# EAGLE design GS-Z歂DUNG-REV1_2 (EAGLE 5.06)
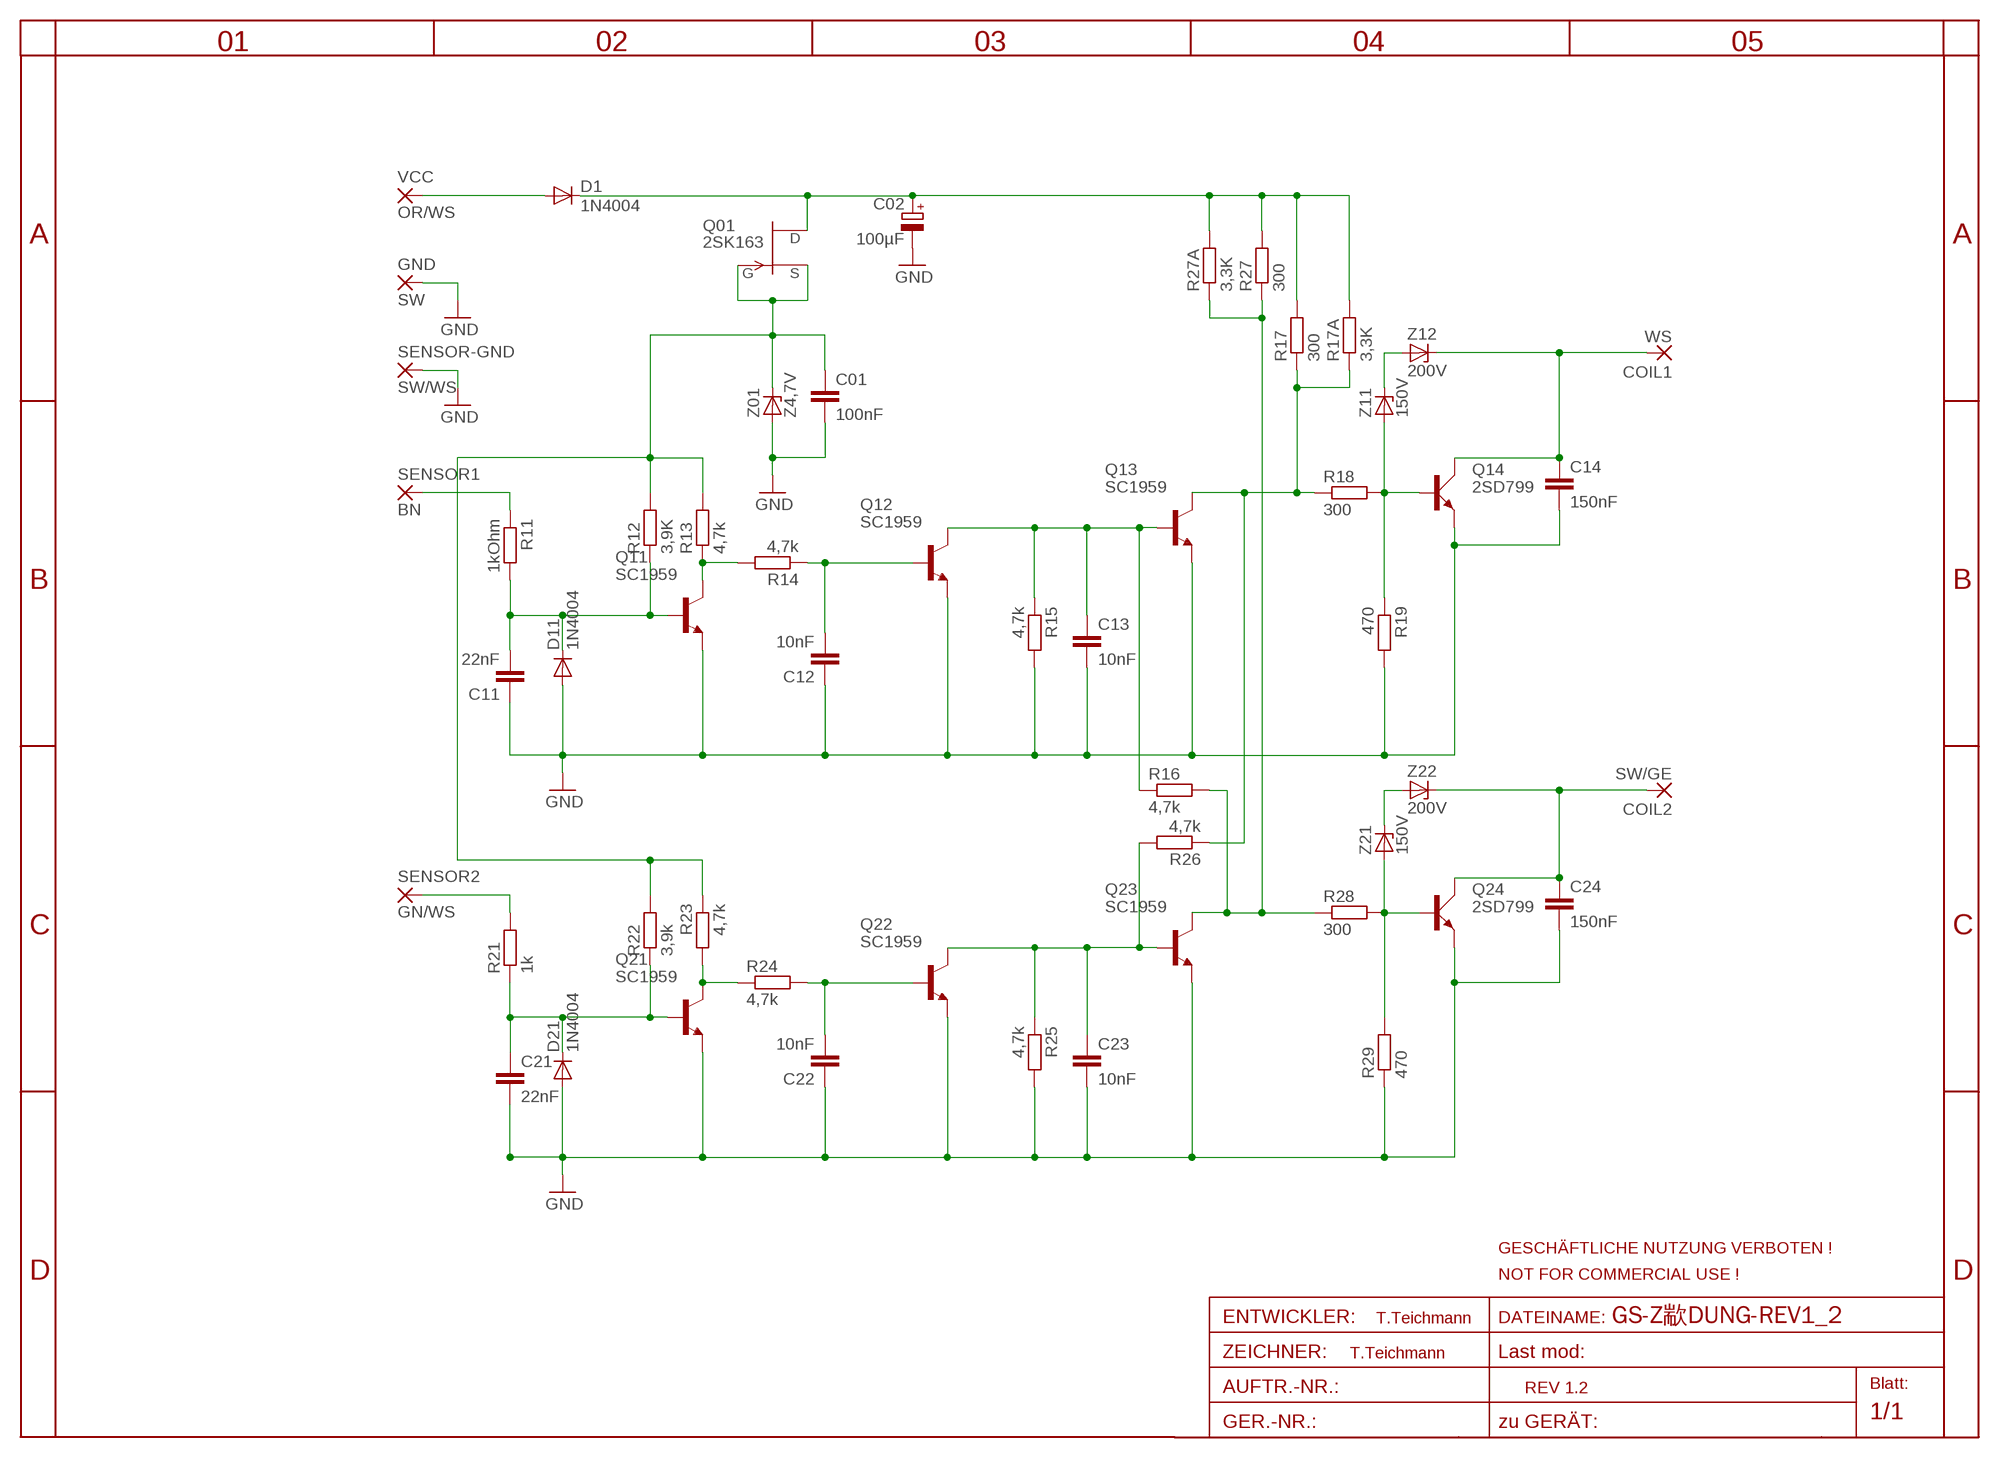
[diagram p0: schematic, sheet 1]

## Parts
C01  100nF  C-EU050-025X075  [C050-025X075]
C02  100µF  CPOL-EUE3.5-8  [E3,5-8]
C11  22nF  C-EU050-025X075  [C050-025X075]
C12  10nF  C-EU050-025X075  [C050-025X075]
C13  10nF  C-EU050-025X075  [C050-025X075]
C14  150nF  C-EU150-064X183  [C150-064X183]
C21  22nF  C-EU050-025X075  [C050-025X075]
C22  10nF  C-EU050-025X075  [C050-025X075]
C23  10nF  C-EU050-025X075  [C050-025X075]
C24  150nF  C-EU150-064X183  [C150-064X183]
COIL1  WS  WIREPAD4,16O1,6  [4,16O1,6]
COIL2  SW/GE  WIREPAD4,16O1,6  [4,16O1,6]
D1  1N4004  1N4148  [DO35-10]
D11  1N4004  1N4148  [DO35-10]
D21  1N4004  1N4148  [DO35-10]
GND  SW  WIREPAD4,16O1,6  [4,16O1,6]
Q01  2SK163  2N3819TO92-DGS  [TO92-]
Q11  SC1959  BC368-NPN-TO92-ECB  [TO92-ECB]
Q12  SC1959  BC368-NPN-TO92-ECB  [TO92-ECB]
Q13  SC1959  BC368-NPN-TO92-ECB  [TO92-ECB]
Q14  2SD799  MJE3055  [TO220AV]
Q21  SC1959  BC368-NPN-TO92-ECB  [TO92-ECB]
Q22  SC1959  BC368-NPN-TO92-ECB  [TO92-ECB]
Q23  SC1959  BC368-NPN-TO92-ECB  [TO92-ECB]
Q24  2SD799  MJE3055  [TO220AV]
R11  1kOhm  R-EU_0207/10  [0207/10]
R12  3,9K  R-EU_0207/10  [0207/10]
R13  4,7k  R-EU_0207/10  [0207/10]
R14  4,7k  R-EU_0207/10  [0207/10]
R15  4,7k  R-EU_0207/10  [0207/10]
R16  4,7k  R-EU_0207/12  [0207/12]
R17  300  R-EU_0617/17  [0617/17]
R17A  3,3K  R-EU_0207/10  [0207/10]
R18  300  R-EU_0207/10  [0207/10]
R19  470  R-EU_0207/10  [0207/10]
R21  1k  R-EU_0207/10  [0207/10]
R22  3,9k  R-EU_0207/10  [0207/10]
R23  4,7k  R-EU_0207/10  [0207/10]
R24  4,7k  R-EU_0207/10  [0207/10]
R25  4,7k  R-EU_0207/10  [0207/10]
R26  4,7k  R-EU_0207/12  [0207/12]
R27  300  R-EU_0617/17  [0617/17]
R27A  3,3K  R-EU_0207/10  [0207/10]
R28  300  R-EU_0207/10  [0207/10]
R29  470  R-EU_0207/10  [0207/10]
SENSOR1  BN  WIREPAD3,81/1,4  [3,81/1,4]
SENSOR2  GN/WS  WIREPAD3,81/1,4  [3,81/1,4]
SENSOR-GND  SW/WS  WIREPAD3,81/1,4  [3,81/1,4]
VCC  OR/WS  WIREPAD4,16O1,6  [4,16O1,6]
Z01  Z4,7V  ZENER-DIODEDO35Z10  [DO35Z10]
Z11  150V  ZENER-DIODEZD-7.5  [ZDIO-7.5]
Z12  200V  ZENER-DIODEZD-7.5  [ZDIO-7.5]
Z21  150V  ZENER-DIODEZD-7.5  [ZDIO-7.5]
Z22  200V  ZENER-DIODEZD-7.5  [ZDIO-7.5]

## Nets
GND: C01.2 C02.- C11.1 C12.1 C13.2 C14.2 C21.2 C22.1 C23.2 C24.2 D11.A D21.A GND.1(P) Q11.E Q12.E Q13.E Q14.E Q21.E Q22.E Q23.E Q24.E R15.2 R19.2 R25.2 R29.1 SENSOR-GND.1(P) Z01.A
N$1: Q14.B R18.2 R19.1 Z11.A
N$2: C01.1 Q01.1(S) Q01.2(G) R12.2 R13.2 R22.2 R23.1 Z01.C
N$3: Z11.C Z12.A
N$5: C11.2 D11.C Q11.B R11.2 R12.1
N$8: Q11.C R13.1 R14.2
N$9: C12.2 Q12.B R14.1
N$10: C13.1 Q12.C Q13.B R15.1 R16.1
N$12: C14.1 COIL1.1(P) Q14.C Z12.C
N$13: Q21.C R23.2 R24.1
N$15: C21.1 D21.C Q21.B R21.1 R22.1
N$17: C24.1 COIL2.1(P) Q24.C Z22.C
N$19: Z21.C Z22.A
N$21: C23.1 Q22.C Q23.B R25.1 R26.2
N$24: Q23.C R16.2 R27.1 R27A.1 R28.1
N$25: C02.+ D1.C Q01.3(D) R17.2 R17A.2 R27.2 R27A.2
N$28: Q24.B R28.2 R29.2 Z21.A
N$32: Q13.C R17.1 R17A.1 R18.1 R26.1
N$34: D1.A VCC.1(P)
N$44: C22.2 Q22.B R24.2
N$63: R21.2 SENSOR2.1(P)
SENSOR1: R11.1 SENSOR1.1(P)

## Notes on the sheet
- GESCHÄFTLICHE NUTZUNG VERBOTEN !
- NOT FOR COMMERCIAL USE !
- T.Teichmann
- T.Teichmann
- REV 1.2

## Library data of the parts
C01 C11-C14 C21-C24 = rcl:C-EU: CAPACITOR, European symbol
C02 = rcl:CPOL-EU: POLARIZED CAPACITOR, European symbol
COIL1 COIL2 GND SENSOR1 SENSOR2 SENSOR-GND VCC = wirepad:WIREPAD: Wire PAD connect wire on PCB
D1 D11 D21 = diode:1N4148: DIODE
Q01 = transistor-fet:2N3819: N-Channel Junction FET
Q11-Q13 Q21-Q23 = transistor-neu-to92:*-NPN-: NPN Transistror
Q14 Q24 = transistor-power:MJE3055: NPN TRANSISTOR
R11-R17 R17A R18 R19 R21-R27 R27A R28 R29 = rcl:R-EU_: RESISTOR, European symbol
Z01 Z11 Z12 Z21 Z22 = diode:ZENER-DIODE: Z-Diode

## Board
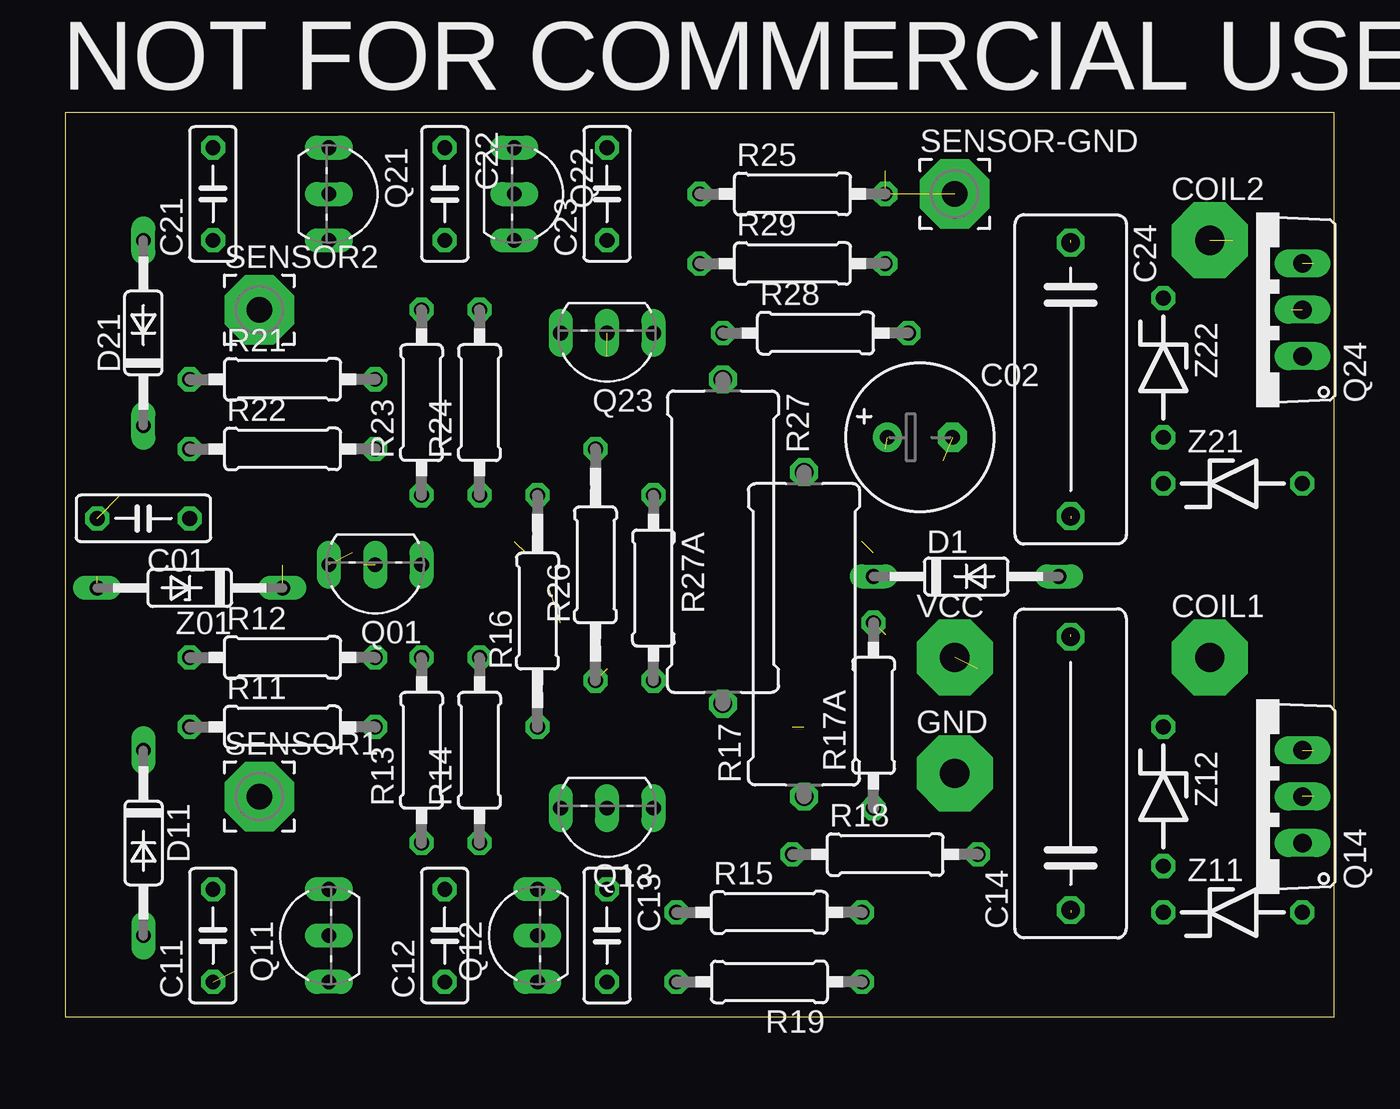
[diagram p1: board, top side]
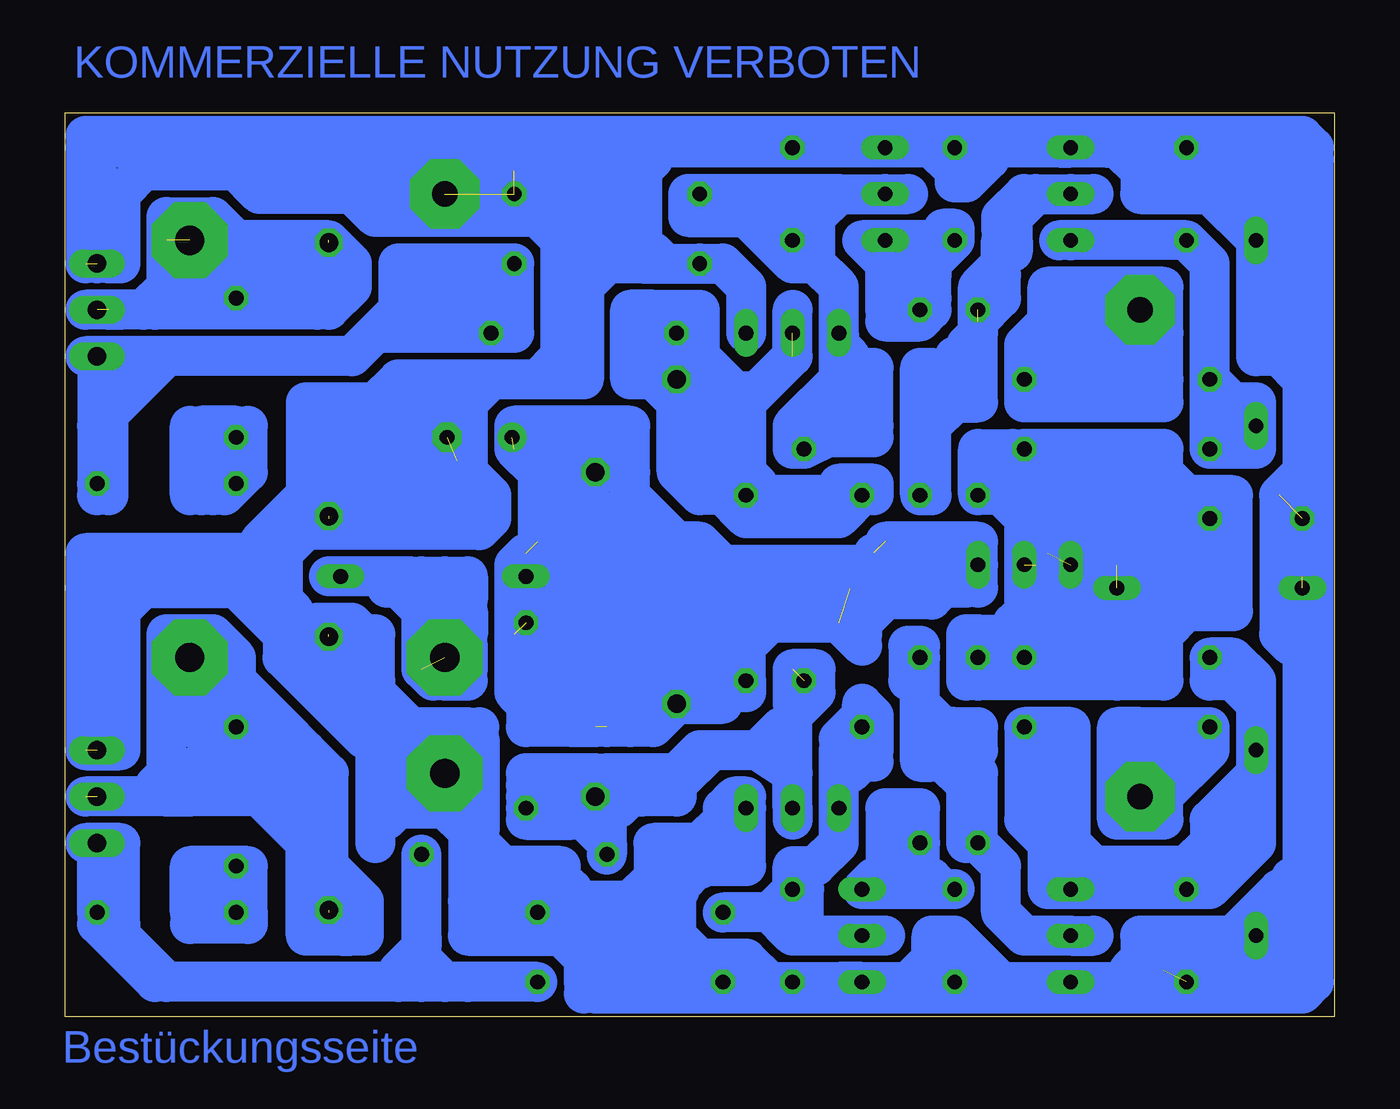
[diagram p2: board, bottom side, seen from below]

Size 69.52 x 49.52 mm. Coordinates in mm from the lower left corner, seen from the top.
Outline: 0,0 69.52,0 69.52,49.52 0,49.52 0,0
Copper layers (1*16): Top 0.035mm / dielectric 1.5mm / Bottom 0.035mm
Design rules "default": minimum track width 10mil, minimum drill 24mil, track to track 8mil, track to pad 8mil, pad to pad 8mil, via to via 8mil, smd to smd 8mil, copper to edge 40mil, drill to drill 8mil, minimum pad ring 10mil, minimum via ring 8mil, stop-mask expansion 4mil, vias tented up to drill 0mil, thermal gap 10mil

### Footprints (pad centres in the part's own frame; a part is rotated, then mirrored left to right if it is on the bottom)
C050-025X075 = drill 0.813 octagon: 1 -2.54,0; 2 2.54,0
E3,5-8 = drill 0.813 pad 1.6 round: + -1.778,0 | drill 0.813 pad 1.6 octagon: - 1.778,0
C150-064X183 = drill 1.016 octagon: 1 -7.493,0; 2 7.493,0
4,16O1,6 = drill 1.6 pad 4.166 octagon: 1 0,0
DO35-10 = drill 0.813 long: A 5.08,0; C -5.08,0
TO92- = drill 0.813 long: 1 2.54,0; 2 0,0; 3 -2.54,0
TO92-ECB = drill 0.813 long: B 2.54,0; C 0,0; E -2.54,0
TO220AV = drill 1.016 long: B -2.54,-2.54; C 0,-2.54; E 2.54,-2.54
0207/10 = drill 0.813 octagon: 1 -5.08,0; 2 5.08,0
0207/12 = drill 0.813 octagon: 1 -6.35,0; 2 6.35,0
0617/17 = drill 1.016 octagon: 1 -8.89,0; 2 8.89,0
3,81/1,4 = drill 1.397 pad 3.81 octagon: 1 0,0
DO35Z10 = drill 0.813 long: A 5.08,0; C -5.08,0
ZDIO-7.5 = drill 0.813 octagon: A 3.81,0; C -3.81,0

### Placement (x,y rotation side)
C01  4.28,27.3 180 top
C02  46.82,31.74 0 top
C11  8.09,4.44 90 top
C12  20.79,4.44 90 top
C13  29.68,4.44 270 top
C14  55.08,13.33 90 top
C21  8.09,45.08 90 top
C22  20.79,45.08 270 top
C23  29.68,45.08 90 top
C24  55.08,34.92 270 top
COIL1  62.7,19.68 0 top
COIL2  62.7,42.54 0 top
D1  49.37,24.12 0 top
D11  4.28,9.52 270 top
D21  4.28,37.46 90 top
GND  48.73,13.33 0 top
Q01  16.98,24.76 180 top
Q11  14.44,4.44 90 top
Q12  25.87,4.44 90 top
Q13  29.68,11.42 180 top
Q14  65.24,12.06 90 top
Q21  14.44,45.08 270 top
Q22  24.6,45.08 270 top
Q23  29.68,37.46 180 top
Q24  65.24,38.73 90 top
R11  11.9,15.87 0 top
R12  11.9,19.68 0 top
R13  19.52,14.6 90 top
R14  22.7,14.6 90 top
R15  38.57,5.71 0 top
R16  25.87,22.22 90 top
R17  40.48,20.95 90 top
R17A  44.28,16.5 90 top
R18  44.92,8.88 0 top
R19  38.57,1.9 180 top
R21  11.9,34.92 0 top
R22  11.9,31.11 0 top
R23  19.52,33.65 90 top
R24  22.7,33.65 90 top
R25  39.84,45.08 0 top
R26  29.04,24.76 90 top
R27  36.03,26.03 270 top
R27A  32.22,23.49 270 top
R28  41.11,37.46 0 top
R29  39.84,41.27 0 top
SENSOR1  10.63,12.06 0 top
SENSOR2  10.63,38.73 0 top
SENSOR-GND  48.73,45.08 0 top
VCC  48.73,19.68 0 top
Z01  6.82,23.49 180 top
Z11  63.97,5.71 0 top
Z12  60.16,12.06 270 top
Z21  63.97,29.2 0 top
Z22  60.16,35.55 270 top

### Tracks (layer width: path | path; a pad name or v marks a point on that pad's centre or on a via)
GND  (10 unrouted)
  Bottom 2.184: 23.96,1.9 23.33,1.9 22.06,3.17 | Q12.E 23.96,1.9 | 18.25,1.9 Q11.E 11.27,1.9 11.27,2.53 10.63,3.17 10.63,4.44 5.55,4.44 3.01,6.98 3.01,5.71 D11.A 6.18,2.53 9.36,2.53 10,1.9 1.74,1.9 1.74,6.98 2.38,7.62 | 18.25,1.9 C12.1 23.96,1.9 | C22.1 22.06,47.62 | 22.06,47.62 Q22.E | 15.08,47.62 18.25,47.62 | 15.08,47.62 Q21.E | 18.25,47.62 C22.1 | C22.1 20.79,46.35 | 20.79,45.71 20.79,46.35 | 18.25,47.62 20.79,45.71 | 20.79,46.35 22.06,47.62 | 20.79,4.44 20.79,3.17 | 22.06,3.17 20.79,4.44 | 18.25,1.9 20.79,4.44 | 20.79,4.44 22.06,4.44 22.06,3.17 | Q12.E 27.14,1.9 | 30.95,1.9 C13.2 | 30.95,1.9 R19.2 37.3,1.9 | 30.95,1.9 32.22,3.17 34.76,3.17 36.03,4.44 36.03,6.98 34.76,8.25 32.22,8.25 Q13.E | Q13.E 33.49,11.42 | 33.49,11.42 33.49,10.79 | 33.49,10.79 33.49,9.52 | 33.49,10.79 34.76,9.52 37.3,9.52 37.3,7.62 38.57,6.35 41.11,6.35 | 47.46,15.87 46.82,15.23 | 51.27,15.87 50.63,15.87 | 50.63,15.87 48.09,15.87 | 48.09,15.87 47.46,15.87 | 51.27,15.87 53.81,19.68 | 30.95,1.9 Q12.E | 37.3,1.9 39.84,1.9 42.38,4.44 | 42.38,4.44 47.46,4.44 47.46,6.35 | 47.46,10.15 48.73,12.06 51.27,12.06 | 52.54,12.06 51.27,12.06 | 52.54,15.87 52.54,12.06 | 52.54,15.87 52.54,17.14 | 47.46,15.87 GND.1 | 51.27,12.06 51.27,15.87 | 52.54,12.06 52.54,10.79 | 52.54,10.79 52.54,9.52 | 52.54,15.87 55.08,18.41 56.35,18.41 | 57.62,19.68 56.35,18.41 | 57.62,19.68 56.35,19.68 55.08,20.95 57.62,20.95 | 57.62,20.95 57.62,19.68 | 57.62,20.95 60.16,23.49 65.24,23.49 66.51,22.22 | 66.51,22.22 67.78,20.95 67.78,15.87 | 66.51,22.22 66.51,14.6 68.41,14.6 68.41,23.49 | 68.41,23.49 68.41,25.39 58.25,25.39 | 53.81,29.84 55.08,29.84 56.35,28.57 | 68.41,23.49 67.78,23.49 66.51,22.22 | 56.35,32.38 50,32.38
  Bottom 2.184: 56.35,32.38 56.35,28.57 | 56.35,27.93 56.35,27.3 58.25,25.39 | 56.35,33.65 56.35,32.38 | 56.35,33.65 52.54,33.65 51.27,34.92 46.19,34.92 | 43.65,34.92 46.19,34.92 | 68.41,41.27 68.41,47.62 56.35,47.62 | 56.35,47.62 53.81,47.62 | 53.81,45.08 58.89,45.08 60.16,46.35 65.24,46.35 66.51,45.08 66.51,41.27 67.14,41.27 | 53.81,45.08 52.54,43.81 43.65,43.81 42.38,42.54 42.38,41.27 | 42.38,41.27 42.38,36.19 43.65,34.92 | 43.65,34.92 41.11,34.92 41.11,40 39.84,41.27 | 37.94,41.27 39.84,41.27 | Q23.E 32.22,40 33.49,41.27 R29.1 36.66,41.27 | 38.57,45.08 38.57,43.81 | 38.57,45.08 38.57,46.35 | 37.94,41.27 36.66,41.27 | 37.94,41.27 38.57,45.08 | 37.94,47.62 37.94,46.35 | 37.94,46.35 37.94,41.91 | 37.94,41.91 37.94,41.27 | 39.84,41.27 39.84,46.35 | 42.38,41.27 42.38,45.08 | 42.38,45.08 41.11,46.35 | 43.65,47.62 56.35,47.62 | 37.94,47.62 43.65,47.62 | Q22.E C23.2 37.94,47.62 | C22.1 Q22.E | 43.65,47.62 42.38,46.35 | 43.65,47.62 44.92,46.35 58.89,46.35 | 42.38,45.08 53.81,45.08 | 42.38,4.44 R15.2 46.19,5.71 | 37.3,1.9 41.11,5.71 42.38,5.71 | 42.38,6.98 46.19,6.98 47.46,6.35 | 51.27,12.06 51.91,11.42 | 52.54,10.79 51.91,11.42 | 46.82,15.23 46.82,10.15 | 48.09,15.87 46.82,15.23 | 48.09,15.87 48.09,15.23 46.82,15.87 | 50.63,15.87 54.45,19.68 | 57.62,22.22 56.98,22.22 57.62,22.86 57.62,25.39 56.35,26.66 | 56.35,26.66 55.71,27.3 55.08,27.3 | 46.82,28.57 46.82,26.66 | 46.82,29.2 46.82,28.57 | 46.82,29.2 48.09,30.47 48.09,33.02 46.19,34.92 | 46.82,26.66 56.35,26.66 | 46.82,26.66 46.19,27.3 46.19,28.57 46.82,29.2 | 46.82,28.57 53.81,28.57 54.45,27.93 | 58.25,26.66 58.25,25.39 | 56.35,27.93 58.25,26.66 | 56.35,28.57 56.35,27.93 | 56.35,33.65 56.35,28.57
  Bottom 2.184: 56.35,18.41 53.17,15.23 | 48.73,11.42 48.09,11.42 | 51.27,11.42 48.73,11.42 | 51.91,11.42 51.27,11.42 | 51.27,11.42 51.91,10.79 | 47.46,10.15 47.46,6.35 | 47.46,10.15 48.73,11.42 | 48.09,15.87 48.73,13.96 47.46,14.6 | 33.49,11.42 32.85,12.06 32.22,12.06 Q13.E | 58.89,26.03 58.25,26.66 | 58.89,26.03 58.25,26.03 56.35,27.93 | 56.35,28.57 58.89,26.03 | 20.79,45.71 20.15,45.71 18.88,46.98 | 1.74,20.31 1.74,7.62 2.38,6.98 | 1.74,20.31 2.38,20.31 3.01,20.95 | 3.01,20.95 3.01,28.57 1.74,29.84 1.74,34.92 | 1.74,34.92 3.01,36.19 4.28,36.19 D21.A 6.82,45.08 | 6.82,45.08 10.63,45.08 10.63,46.35 11.9,47.62 12.54,47.62 | 12.54,47.62 15.08,47.62 | 12.54,47.62 C21.2 1.74,47.62 | 1.74,47.62 1.74,34.92 | 6.82,45.08 6.18,44.45 3.64,44.45 | 1.74,24.12 1.74,20.31 | 1.74,24.12 1.74,29.2 | 1.74,47.62 1.1,46.98 1.1,1.9 1.74,1.27 37.94,1.27 | 37.94,1.27 39.2,1.27 | 3.01,20.95 1.74,22.22 1.74,24.12 | 37.94,1.27 40.48,1.27 41.11,1.9 | 41.11,1.9 41.11,3.81 | 41.11,1.9 41.11,1.27 | 36.66,41.27 37.3,41.91 37.94,41.91 | 37.94,46.35 37.3,46.98 | Q24.E 67.78,46.35
  Bottom 2.54: 34.76,8.25 36.03,8.25 36.03,6.98
N$1
  Bottom 2.184: 50,1.9 50,3.17 | 50,3.17 50,4.44 | 50,4.44 R18.2 | R19.1 47.46,1.9 | 47.46,1.9 50,1.9 | 50,1.9 51.27,1.9 | 51.27,1.9 63.97,1.9 Z11.A | Z11.A Q14.B | 47.46,1.9 48.73,1.9 50,3.17 | 50,3.17 51.27,1.9 | Z11.A 67.78,5.08 64.61,1.9 | 50,4.44 50,3.81 51.27,2.53
N$2  (3 unrouted)
  Bottom 2.184: R12.2 R13.2 18.25,20.95 19.52,20.95 | 11.9,26.03 11.9,25.39 | 11.9,25.39 11.9,24.76 6.82,24.76 | 11.9,27.3 11.9,26.03 | 16.98,29.84 18.25,28.57 | R12.2 16.98,20.95 10.63,20.95 | 16.98,29.84 16.98,27.3 | 16.98,29.84 R22.2 9.36,31.11 9.36,29.84 8.09,28.57 5.55,28.57 5.55,22.22 8.09,22.22 9.36,20.95 | 16.98,29.84 10.63,29.84 | 16.98,27.3 11.9,27.3 | 10.63,19.68 R12.2 | 9.36,20.95 10.63,19.68 | 11.9,26.03 6.82,26.03 | 19.52,18.41 19.52,20.95 | 11.9,18.41 19.52,18.41 | 11.9,18.41 10.63,19.68 | 18.25,28.57 R23.1 19.52,29.84 | 18.25,28.57 16.98,27.3 | 19.52,20.95 20.15,20.95 20.15,18.41 19.52,18.41 | 9.36,20.95 9.36,18.41 11.9,18.41 | 11.9,27.3 C01.1 | 19.52,29.84 19.52,31.11 17.61,31.11 | 16.98,26.66 Q01.2 16.98,22.86 | 16.98,22.86 16.98,22.22 17.61,21.59 | 16.98,22.86 16.34,23.49 6.18,23.49 | 16.34,24.76 15.71,25.39 11.9,25.39 | 19.52,29.84 18.25,29.84
N$3
  Bottom 2.184: Z11.C Z12.A 60.8,8.25 | 60.8,8.25 62.7,8.25 | 62.7,8.25 61.43,6.98 62.7,6.98 | 62.7,6.98 62.7,8.25 | 62.7,6.98 62.7,5.71 Z11.C | Z11.C 59.52,5.71 | 59.52,5.71 59.52,8.25 60.8,8.25 | 59.52,5.71 59.52,5.08 62.7,5.08
N$4
  Bottom 2.184: 47.46,12.06 47.46,15.87
N$5
  Bottom 2.184: 4.28,16.5 D11.C 4.28,13.33 | 4.28,16.5 4.28,18.41 5.55,19.68 R12.1 6.82,18.41 5.55,18.41 4.28,17.14 4.28,16.5 | 4.28,13.33 4.28,9.52 6.82,6.98 C11.2 Q11.B | Q11.B 14.44,8.25 | 14.44,8.25 14.44,9.52 | 14.44,9.52 15.71,10.79 15.71,14.6 | 15.71,14.6 R11.2 | Q11.B 15.71,6.98 15.71,9.52 16.98,10.79 R11.2 | 15.71,15.87 R11.2 | 15.71,15.87 15.71,14.6 | 4.28,13.33 6.82,10.79 6.82,9.52 8.09,8.25 13.17,8.25 | 13.17,8.25 14.44,8.25 | 13.17,8.25 14.44,9.52 | 14.44,9.52 14.44,15.87 15.71,15.87
N$6
  pour Bottom: 66.51,47.62 66.51,45.08
N$7
  Bottom 2.184: 37.94,42.54 38.57,42.54
N$8
  Bottom 2.184: R13.1 19.52,13.33 22.06,15.87 | 22.06,15.87 22.7,13.96 | 13.17,4.44 Q11.C 16.98,4.44 18.25,5.71 18.25,8.25 R13.1 | 22.7,13.96 22.7,16.5 | 22.7,16.5 22.7,17.14 | 22.7,17.14 R14.2 22.7,20.31 23.33,20.31 23.33,18.41 | 21.42,13.96 22.7,15.23 22.7,13.96 | R13.1 20.15,9.52 20.15,12.7 21.42,13.96 | 22.06,15.87 20.79,15.87 | 20.79,15.87 19.52,14.6 19.52,15.87 20.79,15.87 | 21.42,13.96 22.7,16.5 | 20.79,15.87 21.42,15.87 22.7,17.14 | 22.7,13.96 22.06,13.96
N$9
  Bottom 2.184: 22.7,6.98 Q12.B 25.23,7.62 | 22.7,6.98 R14.1 22.7,11.42 24.6,11.42 24.6,8.25 | 22.7,6.98 C12.2 21.42,6.98 22.06,7.62
N$10
  Bottom 2.184: 24.6,4.44 Q12.C 28.41,4.44 | 28.41,4.44 29.68,4.44 | 29.68,4.44 29.68,5.71 | 29.68,5.71 30.95,5.71 | 30.95,5.71 R15.1 | 29.68,4.44 30.95,5.71 | 30.95,5.71 C13.1 | 29.68,5.71 29.68,8.25 28.41,8.25 27.14,9.52 Q13.B 27.14,14.6 R16.1 | R16.1 25.87,16.5 | R16.1 25.87,15.23 | 25.87,15.23 26.5,14.6 | 25.87,16.5 27.14,15.23 | 25.87,15.23 25.87,13.96 26.5,13.33 | 25.87,16.5 25.23,16.5 | 25.23,16.5 25.23,14.6 | 25.23,16.5 25.87,17.14 25.87,16.5 | 28.41,4.44 29.04,4.44 29.04,6.98
N$11
  Bottom 2.184: 68.41,9.52 66.51,9.52 66.51,5.08
N$12  (2 unrouted)
  Bottom 2.184: 63.97,12.06 68.41,12.06 | 55.08,8.25 55.08,5.71 55.08,4.44 | 55.08,8.25 55.08,13.33 56.35,14.6 | 60.16,19.68 COIL1.1 | 56.35,14.6 57.62,15.87 | 57.62,15.87 Z12.C | Z12.C 60.16,18.41 | 60.16,18.41 60.16,19.68 | Z12.C 63.97,12.06 | 57.62,15.87 60.16,18.41 | 60.16,19.68 61.43,20.95 63.97,20.95 63.97,13.33 | 55.08,4.44 56.35,4.44 56.35,9.52 | 56.35,12.06 56.35,9.52 | 56.35,14.6 56.35,12.06 | 56.35,12.06 58.89,12.06 | 58.89,12.06 62.7,12.06 | 62.7,12.06 63.97,13.33 | 63.97,12.06 62.7,12.06 | 56.35,9.52 58.89,12.06 | 54.45,4.44 55.08,4.44 | 54.45,4.44 53.81,4.44 53.81,6.35 54.45,6.98 | 63.97,13.33 64.61,12.7 | 54.45,4.44 53.17,4.44 53.17,6.35 55.08,8.25
N$13  (1 unrouted)
  Bottom 2.184: 13.17,45.08 Q21.C 16.34,45.08 17.61,43.81 17.61,42.54 | 22.7,31.74 R24.1 22.06,28.57 22.06,32.38 | 22.7,31.74 22.06,32.38 | 22.06,32.38 20.79,33.65 | 20.79,33.65 20.15,36.83 | 20.15,36.83 19.52,37.46 | 19.52,38.09 19.52,40 18.25,41.27 18.25,42.54 17.61,42.54 | 17.61,42.54 17.61,41.91 | 20.79,33.65 19.52,33.65 19.52,37.46 | 19.52,38.09 18.25,39.37 18.25,40.63 | 19.52,37.46 19.52,38.09 | 20.15,36.83 20.15,34.28 20.79,33.65 | 20.79,33.65 20.79,36.19 | 22.7,31.74 22.7,35.55 22.06,35.55
N$14
  pour Bottom: 62.7,15.87 62.7,13.33
N$15
  Bottom 2.184: 6.82,32.38 R22.1 4.28,31.11 D21.C | 6.82,32.38 R21.1 | D21.C 6.82,32.38 | 15.08,42.54 Q21.B C21.1 6.82,41.27 R21.1 | D21.C 4.28,33.65 5.55,33.65 R21.1
N$16
  Bottom 2.184: 6.18,3.17 3.01,3.17 2.38,3.81
N$17  (3 unrouted)
  Bottom 2.184: 67.14,38.73 66.51,38.73 | 67.14,38.73 68.41,38.73 | 65.24,38.73 63.97,40 | 60.16,42.54 55.08,42.54 53.81,41.27 53.81,40 55.08,38.73 Z22.C | 60.16,42.54 63.97,42.54 | Z22.C 60.16,40 | 60.16,40 60.16,41.27 | 60.16,41.27 60.16,42.54 | 63.97,40 62.7,41.27 | 63.97,40 63.97,42.54 | Z22.C 65.24,38.73 | 60.16,40 61.43,40 | 60.16,41.27 61.43,41.27 | 60.16,42.54 61.43,43.81 63.97,43.81 63.97,42.54 | 65.24,38.73 67.14,38.73
N$18
  Bottom 2.184: 50,13.33 50,15.87
N$19
  Bottom 2.184: 61.43,32.38 60.16,32.38 Z22.A Z21.C 60.8,28.57 | 61.43,32.38 61.43,28.57 60.8,28.57 | 61.43,32.38 62.06,32.38 62.06,28.57 60.8,28.57 | 60.8,28.57 59.52,29.84 59.52,32.38
N$20
  Bottom 2.184: 55.71,38.73 64.61,38.73
N$21
  Bottom 2.184: 29.68,32.38 27.14,32.38 | R26.2 29.68,32.38 | 25.87,33.65 26.5,33.02 | 26.5,33.02 27.14,32.38 | 25.87,33.65 27.14,35.55 | Q23.B 27.14,40 28.41,41.27 | 28.41,41.27 C23.1 29.68,43.81 | 23.33,45.08 Q22.C 27.14,45.08 | 27.14,45.08 29.68,45.08 | 29.68,45.08 34.12,45.08 | 34.12,45.08 R25.1 33.49,43.81 32.22,43.81 | 29.68,43.81 29.68,45.08 | R26.2 29.68,31.11 29.68,32.38 | 27.77,31.74 R26.2 | 25.87,32.38 27.77,31.74 | 25.87,32.38 25.87,33.02 | 25.87,33.02 25.87,33.65 | 28.41,41.27 29.68,41.27 32.22,43.81 | 28.41,41.27 28.41,43.81 27.14,45.08 | 27.14,34.92 27.14,35.55 | 27.14,35.55 Q23.B | 27.14,32.38 27.14,34.92 | 29.68,32.38 27.14,34.92 | 25.23,31.74 25.87,32.38 | 25.23,31.74 27.77,31.74 | 25.87,32.38 25.23,32.38 | 27.14,35.55 25.23,35.55 25.23,32.38 | 25.23,31.74 25.23,32.38 | 25.23,32.38 25.87,34.28 | 25.87,33.02 26.5,33.02 | Q23.B 27.14,36.83 26.5,36.19 | 34.12,45.08 35.39,45.08 35.39,43.81 34.76,43.81 | 34.76,43.81 34.12,43.81 | 32.22,43.81 29.68,43.81 | 34.76,43.81 32.22,43.81
N$22
  Bottom 2.184: 41.11,41.27 41.11,45.08
N$23
  Bottom 2.184: 1.1,47.62 1.74,48.26 68.41,48.26
N$24  (1 unrouted)
  Bottom 2.184: 29.68,38.73 29.68,36.19 31.58,34.28 | R27.1 R28.1 | 33.49,34.28 32.85,34.28 | 32.85,34.28 31.58,34.28 | R16.2 R27A.1 | R27A.1 33.49,28.57 | 33.49,28.57 34.76,28.57 36.03,29.84 36.03,33.65 | R27.1 36.03,33.65 | R27.1 37.3,34.92 | 37.3,34.92 37.3,38.73 | 37.3,38.73 34.76,38.73 34.76,36.19 32.85,34.28 | 33.49,33.65 33.49,34.28 | 33.49,33.65 34.76,32.38 34.76,29.84 | 33.49,33.65 33.49,29.84 R27A.1 | 37.3,34.92 38.57,34.92 38.57,38.73 37.3,38.73 | 33.49,28.57 32.22,27.3 27.14,27.3 R16.2 | 36.03,33.65 37.3,34.92 | 31.58,34.28 32.22,33.65 32.22,29.84 31.58,29.2 | R16.2 25.23,28.57 25.23,29.2 27.14,29.2 | 33.49,34.28 R27.1
N$25  (6 unrouted)
  Bottom 2.184: 43.65,29.84 R17.2 38.57,29.84 | 44.92,32.38 44.92,31.11 43.65,29.84 | R27.2 37.3,15.87 | 35.39,17.77 R27.2 | 35.39,17.77 33.49,18.41 33.49,17.14 R27.2 | 38.57,17.14 38.57,18.41 39.2,19.04 | 37.3,15.87 38.57,17.14 | 38.57,28.57 38.57,29.84 | 38.57,28.57 38.57,27.3 | 39.2,19.04 39.84,19.68 39.84,15.87 38.57,15.87 | 38.57,28.57 36.03,26.03 34.76,26.03 33.49,24.76 25.23,24.76 | 38.57,29.84 38.57,32.38 44.92,32.38 | 44.92,32.38 41.11,30.47 43.65,29.84 | 19.52,23.49 Q01.3 19.52,26.03 24.6,26.03 | 38.57,17.14 38.57,15.87 | 37.3,15.87 38.57,15.87 | 34.76,17.77 35.39,17.77 | 32.22,20.31 R27A.2 32.22,17.77 34.76,17.77 | 25.87,20.31 27.14,21.59 | 34.76,17.77 35.39,17.14 | 44.28,24.76 D1.C 43.65,24.12 43.65,23.49 26.5,23.49 | 44.28,24.76 44.92,24.76 | 44.92,24.76 44.92,20.95 | 44.92,20.95 44.28,20.31 43.02,20.31 42.38,19.68 41.74,19.04 41.74,16.5 41.11,15.87 | 43.02,21.59 R17A.2 | 41.11,15.87 40.48,15.87 | 44.92,24.76 44.28,25.39 44.28,24.76 | 41.11,15.87 41.74,15.87 41.74,17.77 43.65,19.68 44.92,19.68 | 44.92,20.95 44.92,19.68 | 43.65,29.84 43.65,26.03 | 25.23,22.86 25.23,24.76 | 25.23,24.76 25.23,25.39 | 33.49,19.68 34.12,19.04 39.2,19.04 | 34.76,17.77 37.94,17.77 | 44.92,19.68 44.92,17.77 | 44.92,17.77 44.28,17.14 44.28,15.87 38.57,15.87 | 44.92,17.77 43.02,17.77
  Bottom 2.54: 39.84,19.68 42.38,19.68
N$26
  Bottom 2.184: 25.23,13.96 26.5,13.96
N$27
  Bottom 2.184: 35.39,36.19 34.76,35.55 34.12,35.55
N$28
  Bottom 2.184: Q24.B 66.51,36.19 66.51,34.92 | Q24.B 68.41,36.19 | 46.19,41.27 R29.2 44.92,37.46 52.54,37.46 | 46.19,41.27 46.19,40 | 46.19,40 R28.2 | 63.97,36.19 53.81,36.19 52.54,37.46 | 63.97,36.19 Q24.B | 52.54,37.46 51.27,38.73 51.27,41.27 46.19,41.27 | Q24.B 67.78,32.38 | 67.78,32.38 Z21.A | 46.19,40 50,40 50,38.73 47.46,38.73 | 63.97,36.19 67.78,32.38 | Z21.A 67.14,28.57 67.14,32.38 | Z21.A 67.78,28.57
N$29
  Bottom 2.184: 42.38,12.06 41.11,12.06 40.48,12.7 41.11,12.7
N$30
  Bottom 2.184: 48.73,33.65 51.27,33.65 52.54,32.38
N$32  (1 unrouted)
  Bottom 2.184: 44.28,12.06 43.02,12.06 | 44.28,12.06 44.28,10.79 41.74,10.79 | 43.02,13.33 44.28,12.06 | 40.48,13.33 42.38,13.33 | 42.38,13.33 43.02,13.33 | 43.02,13.33 44.28,13.33 44.28,12.7 | 39.84,9.52 R18.1 | R17.1 39.84,9.52 | 37.94,12.06 R17.1 | 37.94,12.06 36.03,12.06 36.03,12.7 | 36.03,12.7 36.03,13.33 | R17.1 39.84,13.33 38.57,13.33 | 36.03,13.33 38.57,13.33 | 29.68,10.79 Q13.C 29.68,13.33 | 29.68,13.33 29.68,16.5 28.41,17.77 28.41,19.04 29.68,19.04 29.68,17.14 | 36.03,13.33 34.76,14.6 34.12,14.6 | 31.58,14.6 30.31,15.87 | 29.68,13.33 31.58,14.6 | 31.58,14.6 30.95,14.6 | 37.94,12.06 38.57,12.06 39.2,11.42 | 41.74,11.42 R17A.1 | 41.74,11.42 40.48,11.42 | 39.84,9.52 41.74,11.42 | 34.12,14.6 36.03,12.7 | 31.58,14.6 34.12,14.6 | 39.84,9.52 39.84,10.79 | 42.38,13.33 38.57,13.33
N$33
  pour Bottom: 60.16,1.9 62.7,1.9
N$34  (1 unrouted)
  Bottom 0.406: 47.46,19.68 VCC.1 | 49.37,19.68 VCC.1 | 48.73,20.95 VCC.1
  Bottom 2.184: 47.46,20.95 47.46,22.22 48.09,22.86 | 51.91,23.49 51.27,23.49 50,22.22 50,19.04 49.37,18.41 48.73,18.41 | 48.73,18.41 48.09,18.41 47.46,19.04 47.46,19.68 47.46,20.31 48.09,20.95 48.09,21.59 50.63,24.12 51.27,24.12 | 51.27,24.12 D1.A 55.08,24.12 | 51.27,24.12 50,24.12 | 50,24.12 48.73,24.12 48.73,23.49 48.09,22.86 | 48.09,22.86 48.09,22.22 | 50,24.12 47.46,24.12 47.46,22.86 | 48.73,18.41 47.46,18.41
N$35
  Bottom 2.184: 62.7,28.57 62.7,32.38
N$36
  Bottom 2.184: 67.14,5.71 67.14,8.88
N$37
  Bottom 2.184: 18.25,43.17 18.25,43.81 16.98,45.08
N$38
  Bottom 2.184: 62.7,15.87 62.7,18.41
N$39
  Bottom 2.184: 61.43,15.87 61.43,18.41
N$40
  Bottom 2.184: 57.62,13.33 61.43,13.33
N$41
  Bottom 2.184: 57.62,14.6 60.16,14.6
N$42
  Bottom 2.184: 37.3,3.17 36.03,3.17 | 37.3,3.17 38.57,4.44 | 37.3,3.17 37.3,5.71 39.84,5.71
N$43
  Bottom 2.184: 44.28,8.25 44.92,8.25 | 44.28,8.25 42.38,8.25 42.38,7.62 41.74,6.98 | 44.28,8.25 45.55,8.25 46.82,9.52
N$44
  Bottom 2.184: 23.96,38.09 22.7,38.09 22.06,38.73 | 23.96,38.09 24.6,38.09 24.6,38.73 | C22.2 Q22.B 25.87,42.54 24.6,41.27 | R24.2 23.33,40 22.06,41.27 | 22.06,41.27 C22.2 | R24.2 24.6,38.73 | 24.6,38.73 24.6,41.27 | R24.2 22.7,40 | R24.2 22.06,39.37 22.06,40.63 | 24.6,38.73 23.96,38.09 | C22.2 20.79,43.17 21.42,43.17 | 22.06,41.27 24.6,41.27
N$45
  pour Bottom: 19.52,15.87 19.52,13.33
N$46
  Bottom 2.184: 39.84,27.3 41.11,28.57
N$49
  Bottom 2.184: 39.84,31.11 41.11,31.11
N$50
  Bottom 2.184: 52.54,18.41 52.54,20.95 53.17,20.95 53.81,21.59 55.71,21.59
N$51
  Bottom 2.184: 47.46,30.47 47.46,33.02
N$52
  Bottom 2.184: 48.09,29.84 53.17,29.84 53.81,29.2
N$54
  Bottom 2.184: 48.73,31.11 55.71,31.11
N$55
  Bottom 2.184: 9.36,28.57 15.71,28.57
N$56
  Bottom 2.184: 13.17,26.03 15.71,26.03
N$58
  Bottom 2.184: 58.25,24.12 67.78,24.12
N$59
  Bottom 2.184: 9.36,46.35 8.73,45.71 3.64,45.71 | 3.64,45.71 3.01,45.71 | 3.64,45.71 3.01,45.08 3.01,38.09
N$60
  Bottom 2.184: 42.38,25.39 42.38,27.93
N$61
  Bottom 2.184: 5.55,9.52 5.55,10.79
N$63
  Bottom 2.184: 14.44,37.46 13.17,38.73 15.71,38.73 | R21.2 13.17,34.92 10.63,37.46 SENSOR2.1 10.63,40 | 10.63,40 11.9,40 | 11.9,38.73 11.9,40 | 11.9,38.73 11.9,37.46 | 10.63,40 9.36,40 9.36,37.46 | 9.36,37.46 11.9,34.92 9.36,34.92 | 14.44,36.19 13.17,36.19 | 16.98,36.19 14.44,36.19 | R21.2 16.98,36.19 | 9.36,34.92 9.36,37.46 | 14.44,36.19 11.9,38.73 | 11.9,40 15.71,40 15.71,38.73 | 15.71,38.73 15.71,38.09 16.98,36.83 16.98,36.19 | R21.2 16.98,33.65 9.36,33.65 9.36,34.92
N$64
  Bottom 2.184: 55.08,40 58.89,40
N$65
  Bottom 2.184: 55.08,41.27 58.89,41.27
N$66
  Bottom 2.184: 41.11,27.3 41.74,27.3
N$71
  Bottom 2.184: 6.82,22.86 7.46,22.22 16.34,22.22
N$73
  Bottom 2.184: 21.42,24.76 24.6,24.76
N$74
  Bottom 2.184: 34.76,25.39 41.74,25.39
N$75
  Bottom 2.184: 32.85,19.68 30.95,21.59 25.87,21.59 | 20.79,24.12 20.15,23.49 21.42,23.49 22.06,22.86 24.6,22.86 25.87,21.59 | 25.87,21.59 25.87,20.95 | 25.87,21.59 26.5,22.22 42.38,22.22
N$76
  Bottom 2.184: 33.49,20.95 43.65,20.95
SENSOR1
  Bottom 2.184: 10.63,15.87 R11.1 | 10.63,15.87 SENSOR1.1 | 10.63,10.79 11.9,10.79 11.9,15.87 10.63,15.87 | 10.63,10.79 10.63,15.87 | 10.63,10.79 9.36,10.79 9.36,12.06 | 9.36,12.06 9.36,13.33 | 9.36,13.33 9.36,14.6 8.09,14.6 | R11.1 8.09,14.6 | 9.36,13.33 8.09,14.6 | R11.1 6.82,14.6 9.36,12.06

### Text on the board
Bottom: KOMMERZIELLE NUTZUNG VERBOTEN | Bestückungsseite
tPlace: NOT FOR COMMERCIAL USE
